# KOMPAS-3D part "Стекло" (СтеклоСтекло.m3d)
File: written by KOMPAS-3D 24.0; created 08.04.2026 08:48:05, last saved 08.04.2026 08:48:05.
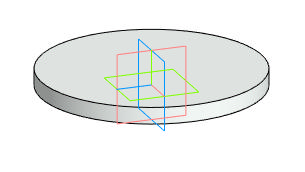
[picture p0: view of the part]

Document properties: Автор: Main; Полное имя файла: D:\DN.ru Аутсерс\Стекло смотровое DN.ru\Исходники\Стекло смотровое DN.ru SG2-34G-F тип В ГОСТ 21836-2021 Ду150 Ру16, углеродистая сталь, фланцевое\СтеклоСтекло.m3d

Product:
- Body: Твердое тело1  | qty 1
- Part/product: Стекло

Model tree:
1. Твердое тело1  (labels: Твердое тело1)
